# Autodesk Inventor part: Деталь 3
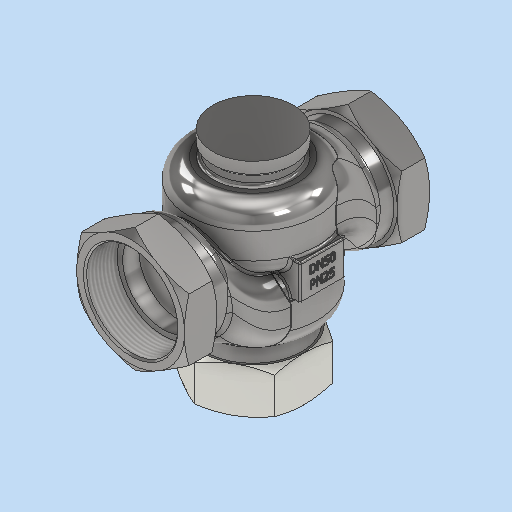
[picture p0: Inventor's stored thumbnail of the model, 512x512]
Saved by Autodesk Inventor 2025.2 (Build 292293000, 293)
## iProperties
Created: 2026-04
Part Number: Деталь 3
Material: Типовые
Document SubType Name: Modeling
Designer: igorr
Density: 1 g/cm^3
Appearance: По умолчанию
Author: igorr
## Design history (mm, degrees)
node "РабПлоскость1"
sketch "Эскиз3"
  geometry: L1 (-33.33, 19.243)-(0, 38.486); L2 (0, 38.486)-(33.33, 19.243); L3 (33.33, 19.243)-(33.33, -19.243); L4 (33.33, -19.243)-(0, -38.486); L5 (0, -38.486)-(-33.33, -19.243); L6 (-33.33, -19.243)-(-33.33, 19.243); C1 r 28.33 at (0, 0); 3 further points
  constraints: 12 end point, 2 coincident, 1 centre point, 1 horizontal alignment, 1 midpoint, 15 other
  dimensions: "d9" = 56.66 diameter of C1; "d10" = 5 dimension on C1
extrude "Выдавливание3" new body sketch "Эскиз3" distance "d11" = 20; taper "d12" = 0 deg
sketch "Эскиз4"
  geometry: C1 r 28.33 at (0, 0) reference; C2 r 31.33 at (0, 0); C3 r 25 at (0, 0); 1 further point
  constraints: 2 centre point, 1 coincident
  dimensions: "d13" = 3 radial gap between concentric circles of C1 C2; "d14" = 50 diameter of C3
extrude "Выдавливание4" join sketch "Эскиз4" distance "d15" = 10; taper "d16" = 0 deg
sketch "Эскиз5"
  geometry: L1 (-28.33, -76)-(28.33, -76) reference; L2 (0, -76)-(0, -84.797); L3 (19.243, -76)-(38.486, -76) reference; L4 (38.486, -76)-(33.486, -76); L5 (33.486, -76)-(40.098, -72.182); L6 (40.098, -72.182)-(40.098, -76); L7 (40.098, -76)-(33.486, -76); L8 (38.486, -76)-(38.486, -56) reference; L9 (38.486, -66)-(40.121, -66); L10 (33.486, -56)-(40.098, -59.818); L11 (40.098, -59.818)-(40.098, -56); L12 (40.098, -56)-(33.486, -56); 2 further points
  constraints: 18 end point, 3 symmetric about line, 2 midpoint, 2 point on line, 1 collinear, 1 horizontal, 1 perpendicular, 1 vertical
  dimensions: "d17" = 5 distance of L3.end L4.end; "d18" = 30 deg angle of L4 L5
revolve "Вращение1" sketch "Эскиз5" stored, may be unused: angle "d19" = 90 deg
node "РабПлоскость4"
sketch "Эскиз13"
  geometry: L1 (22.5, 40)-(-22.5, 40); L2 (-37.5, 25)-(-37.5, 15); L3 (-22.5, 0)-(22.5, 0); L4 (37.5, 15)-(37.5, 25); L5 (37.5, 40)-(-37.5, 0); L6 (-37.5, 40)-(37.5, 0); A1 r 15 centre (22.5, 25) between (37.5, 25) and (22.5, 40); A2 r 15 centre (-22.5, 25) between (-22.5, 40) and (-37.5, 25); A3 r 15 centre (-22.5, 15) between (-37.5, 15) and (-22.5, 0); A4 r 15 centre (22.5, 15) between (22.5, 0) and (37.5, 15); 2 further points
  constraints: 12 end point, 8 point on circle, 8 point on line, 8 tangent, 4 centre point, 3 equal radius, 3 midpoint, 2 parallel, 1 horizontal, 1 perpendicular
  dimensions: "d60" = 75 distance of L5.start L6.start; "d61" = 40 distance of L5.end L6.start; "d62" = 15 radius of A1
feature "Лофт3" sketch "Эскиз13" dims "d63" = 0, "d64" = 90 deg, "d65" = 10, "d66" = 90 deg
  node "Ребра5"
fillet "Сопряжение11" dims "d73" = 7
mirror "Зеркальное отражение6"
mirror "Зеркальное отражение7"
sketch "Эскиз15"
  geometry: C1 r 40 at (0, 0); 1 further point
  constraints: 1 centre point, 1 coincident
  dimensions: "d74" = 80 diameter of C1
extrude "Выдавливание9" join sketch "Эскиз15" distance "d75" = 40; taper "d76" = 0 deg
fillet "Сопряжение12" dims "d77" = 12
sketch "Эскиз16"
  geometry: C1 r 40 at (0, 0); 1 further point
  constraints: 1 centre point, 1 coincident
  dimensions: "d78" = 80 diameter of C1
extrude "Выдавливание10" join sketch "Эскиз16" distance "d79" = 40; taper "d80" = 0 deg
fillet "Сопряжение13" dims "d81" = 12
feature "Комбинировать1"
  node "Твердое тело3"
sketch "Эскиз17"
  geometry: L1 (-11, 14)-(11, 14); L2 (11, 14)-(11, -14); L3 (11, -14)-(-11, -14); L4 (-11, -14)-(-11, 14); L5 (-11, 14)-(11, -14); L6 (11, 14)-(-11, -14); 1 further point
  constraints: 12 end point, 2 midpoint, 2 parallel, 1 horizontal, 1 perpendicular
  dimensions: "d83" = 22 distance of L1.start L1.end; "d84" = 28 distance of L1.end L2.end
extrude "Выдавливание11" join sketch "Эскиз17" distance "d85" = 43; taper "d86" = 0 deg
sketch "Эскиз18"
  geometry: C1 r 30 at (0, 0); 1 further point
  constraints: 1 centre point, 1 coincident
  dimensions: "d88" = 60 diameter of C1
extrude "Выдавливание12" join sketch "Эскиз18" distance "d89" = 10; taper "d90" = 0 deg; dims "d119" = 6.5, "d120" = 0
sketch "Эскиз19"
  geometry: L1 (31.33, -18.088)-(0, -36.177); L2 (0, -36.177)-(-31.33, -18.088); L3 (-31.33, -18.088)-(-31.33, 18.088); L4 (-31.33, 18.088)-(0, 36.177); L5 (0, 36.177)-(31.33, 18.088); L6 (31.33, 18.088)-(31.33, -18.088); C1 r 28.33 at (0, 0); 3 further points
  constraints: 12 end point, 2 coincident, 1 centre point, 1 horizontal alignment, 1 midpoint, 15 other
  dimensions: "d91" = 56.66 diameter of C1; "d92" = 3 dimension on C1
extrude "Выдавливание13" join sketch "Эскиз19" distance "d94" = 28; taper "d95" = 0 deg
sketch "Эскиз20"
  geometry: C1 r 25 at (0, 0); 1 further point
  constraints: 1 centre point, 1 coincident
  dimensions: "d96" = 50 diameter of C1
extrude "Выдавливание14" cut sketch "Эскиз20" distance "d97" = 17; taper "d98" = 0 deg
sketch "Эскиз21"
  geometry: L1 (-78, -36.177)-(-78, -18.088) reference; L2 (-78, -36.177)-(-78, -31.177); L3 (-78, -31.177)-(-75.113, -36.177); L4 (-50, -36.177)-(-78, -36.177) reference; L5 (-75.113, -36.177)-(-78, -36.177); L6 (-78, 18.088)-(-78, -18.088) reference; L7 (-78, 0)-(-83.309, 0); L8 (-64, -36.177)-(-64, -19.962); L9 (-50, -36.177)-(-50, -31.177); L10 (-50, -31.177)-(-52.887, -36.177); L11 (-52.887, -36.177)-(-50, -36.177); 2 further points
  constraints: 16 end point, 2 midpoint, 2 point on line, 2 symmetric about line, 1 collinear, 1 horizontal, 1 vertical
  dimensions: "d99" = 5 distance of L1.start L2.end; "d100" = 30 deg angle of L2 L3
revolve "Вращение2" sketch "Эскиз21" stored, may be unused: angle "d101" = 360 deg
sketch "Эскиз22"
  geometry: C1 r 25 at (0, 0) reference; C2 r 23 at (0, 0); 1 further point
  constraints: 1 centre point, 1 coincident
  dimensions: "d103" = 46 diameter of C2
extrude "Выдавливание15" join sketch "Эскиз22" distance "d104" = 15; taper "d105" = 0 deg; dims "d128" = 4.5, "d129" = 0
sketch "Эскиз23"
  geometry: L1 (-6.439, 7.098)-(5.822, 7.098); L2 (5.822, 7.098)-(5.822, 3.985); L3 (5.822, 3.985)-(-6.439, 3.985); L4 (-6.439, 3.985)-(-6.439, 7.098); 1 further point
  constraints: 2 other
feature "Рельеф1" sketch "Эскиз23" dims "d17" = 5, "d18" = 30 deg, "d106" = 0.5, "d107" = 0
chamfer "Фаска1" distance "d108" = 1; stored, may be unused: second distance "d109" = 2, angle "d110" = 45 deg
sketch "Эскиз24"
  geometry: C1 r 25 at (0, 0); 1 further point
  constraints: 1 centre point, 1 coincident
  dimensions: "d111" = 50 diameter of C1
extrude "Выдавливание16" join sketch "Эскиз24" distance "d112" = 8; taper "d113" = 0 deg
feature "Резьба1" dims "d115" = 150, "d116" = 0
feature "Резьба2" dims "d117" = 24, "d118" = 0
fillet "Сопряжение20" dims "d123" = 2
fillet "Сопряжение22" dims "d125" = 1
fillet "Сопряжение25" dims "d130" = 1
fillet "Сопряжение26" dims "d131" = 1
node "Твердое тело2"
feature "Шаблон Твердое тело2:1"
other parameters: "d8" = -76, "d54" = 33
